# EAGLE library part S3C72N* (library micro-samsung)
S3C72N2/C72N4/P72N4 single-chip CMOS microcontroller has been designed for high performance using Samsung's newest 4-bit CPU core, SAM47 (Samsung Arrangeable Microcontrollers). Source: http://www.samsung.com/Products/Semiconductor/SystemLSI/Microcontrollers/4_bit/S3C7_KS57Series/S3C72N4/um_s3c72n2_cp72n4_v1.pdf
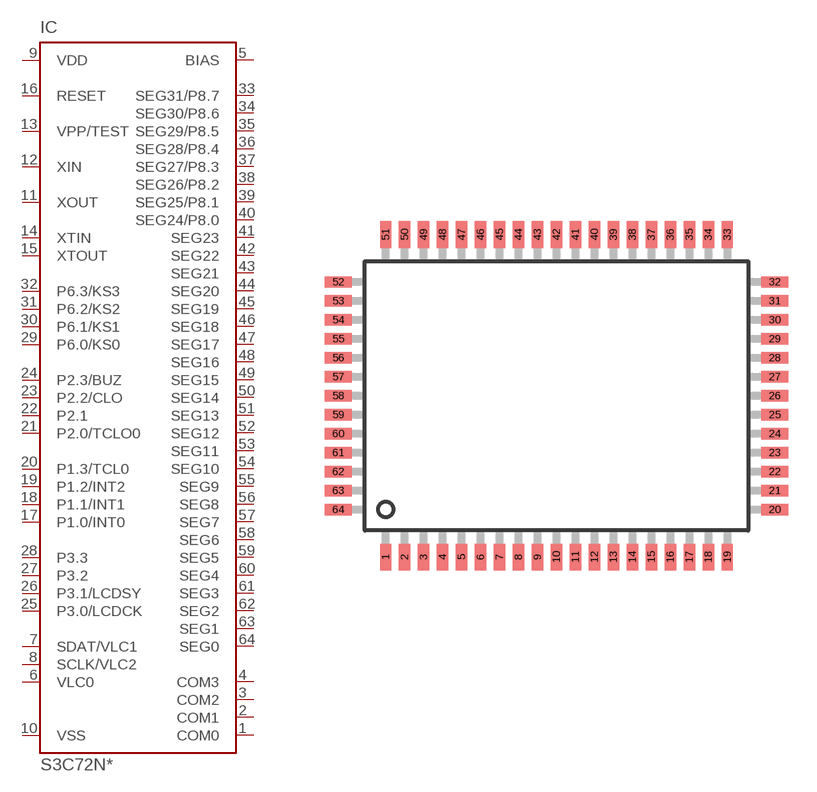
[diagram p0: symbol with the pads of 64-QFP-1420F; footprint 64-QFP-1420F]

Designator prefix IC

## S3C72N2, S3C72N4  [64-QFP-1420F]
1  COM0  out
2  COM1  out
3  COM2  out
4  COM3  out
5  BIAS  pas
6  VLC0  pas
7  SDAT/VLC1  pas
8  SCLK/VLC2  pas
9  VDD  pwr
10  VSS  pwr
11  XOUT  out
12  XIN  in
13  VPP/TEST  in
14  XTIN  pas
15  XTOUT  out
16  RESET  in
17  P1.0/INT0  in
18  P1.1/INT1  in
19  P1.2/INT2  in
20  P1.3/TCL0  in
21  P2.0/TCLO0
22  P2.1
23  P2.2/CLO
24  P2.3/BUZ
25  P3.0/LCDCK
26  P3.1/LCDSY
27  P3.2
28  P3.3
29  P6.0/KS0
30  P6.1/KS1
31  P6.2/KS2
32  P6.3/KS3
33  SEG31/P8.7  out
34  SEG30/P8.6  out
35  SEG29/P8.5  out
36  SEG28/P8.4  out
37  SEG27/P8.3  out
38  SEG26/P8.2  out
39  SEG25/P8.1  out
40  SEG24/P8.0  out
41  SEG23  out
42  SEG22  out
43  SEG21  out
44  SEG20  out
45  SEG19  out
46  SEG18  out
47  SEG17  out
48  SEG16  out
49  SEG15  out
50  SEG14  out
51  SEG13  out
52  SEG12  out
53  SEG11  out
54  SEG10  out
55  SEG9  out
56  SEG8  out
57  SEG7  out
58  SEG6  out
59  SEG5  out
60  SEG4  out
61  SEG3  out
62  SEG2  out
63  SEG1  out
64  SEG0  out

## Footprint 64-QFP-1420F (pad centres in mm)
64-QFP-1420F source: http://www.samsung.com/Products/Semiconductor/SystemLSI/Microcontrollers/4_bit/S3C7_KS57Series/S3C72N4/um_s3c72n2_cp72n4_v1.pdf
smd 0.6 x 1.4: 1 -9,-8.5; 2 -8,-8.5; 3 -7,-8.5; 4 -6,-8.5; 5 -5,-8.5; 6 -4,-8.5; 7 -3,-8.5; 8 -2,-8.5; 9 -1,-8.5; 10 0,-8.5; 11 1,-8.5; 12 2,-8.5; 13 3,-8.5; 14 4,-8.5; 15 5,-8.5; 16 6,-8.5; 17 7,-8.5; 18 8,-8.5; 19 9,-8.5; 33 9,8.5; 34 8,8.5; 35 7,8.5; 36 6,8.5; 37 5,8.5; 38 4,8.5; 39 3,8.5; 40 2,8.5; 41 1,8.5; 42 0,8.5; 43 -1,8.5; 44 -2,8.5; 45 -3,8.5; 46 -4,8.5; 47 -5,8.5; 48 -6,8.5; 49 -7,8.5; 50 -8,8.5; 51 -9,8.5
smd 1.4 x 0.6: 20 11.5,-6; 21 11.5,-5; 22 11.5,-4; 23 11.5,-3; 24 11.5,-2; 25 11.5,-1; 26 11.5,0; 27 11.5,1; 28 11.5,2; 29 11.5,3; 30 11.5,4; 31 11.5,5; 32 11.5,6; 52 -11.5,6; 53 -11.5,5; 54 -11.5,4; 55 -11.5,3; 56 -11.5,2; 57 -11.5,1; 58 -11.5,0; 59 -11.5,-1; 60 -11.5,-2; 61 -11.5,-3; 62 -11.5,-4; 63 -11.5,-5; 64 -11.5,-6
